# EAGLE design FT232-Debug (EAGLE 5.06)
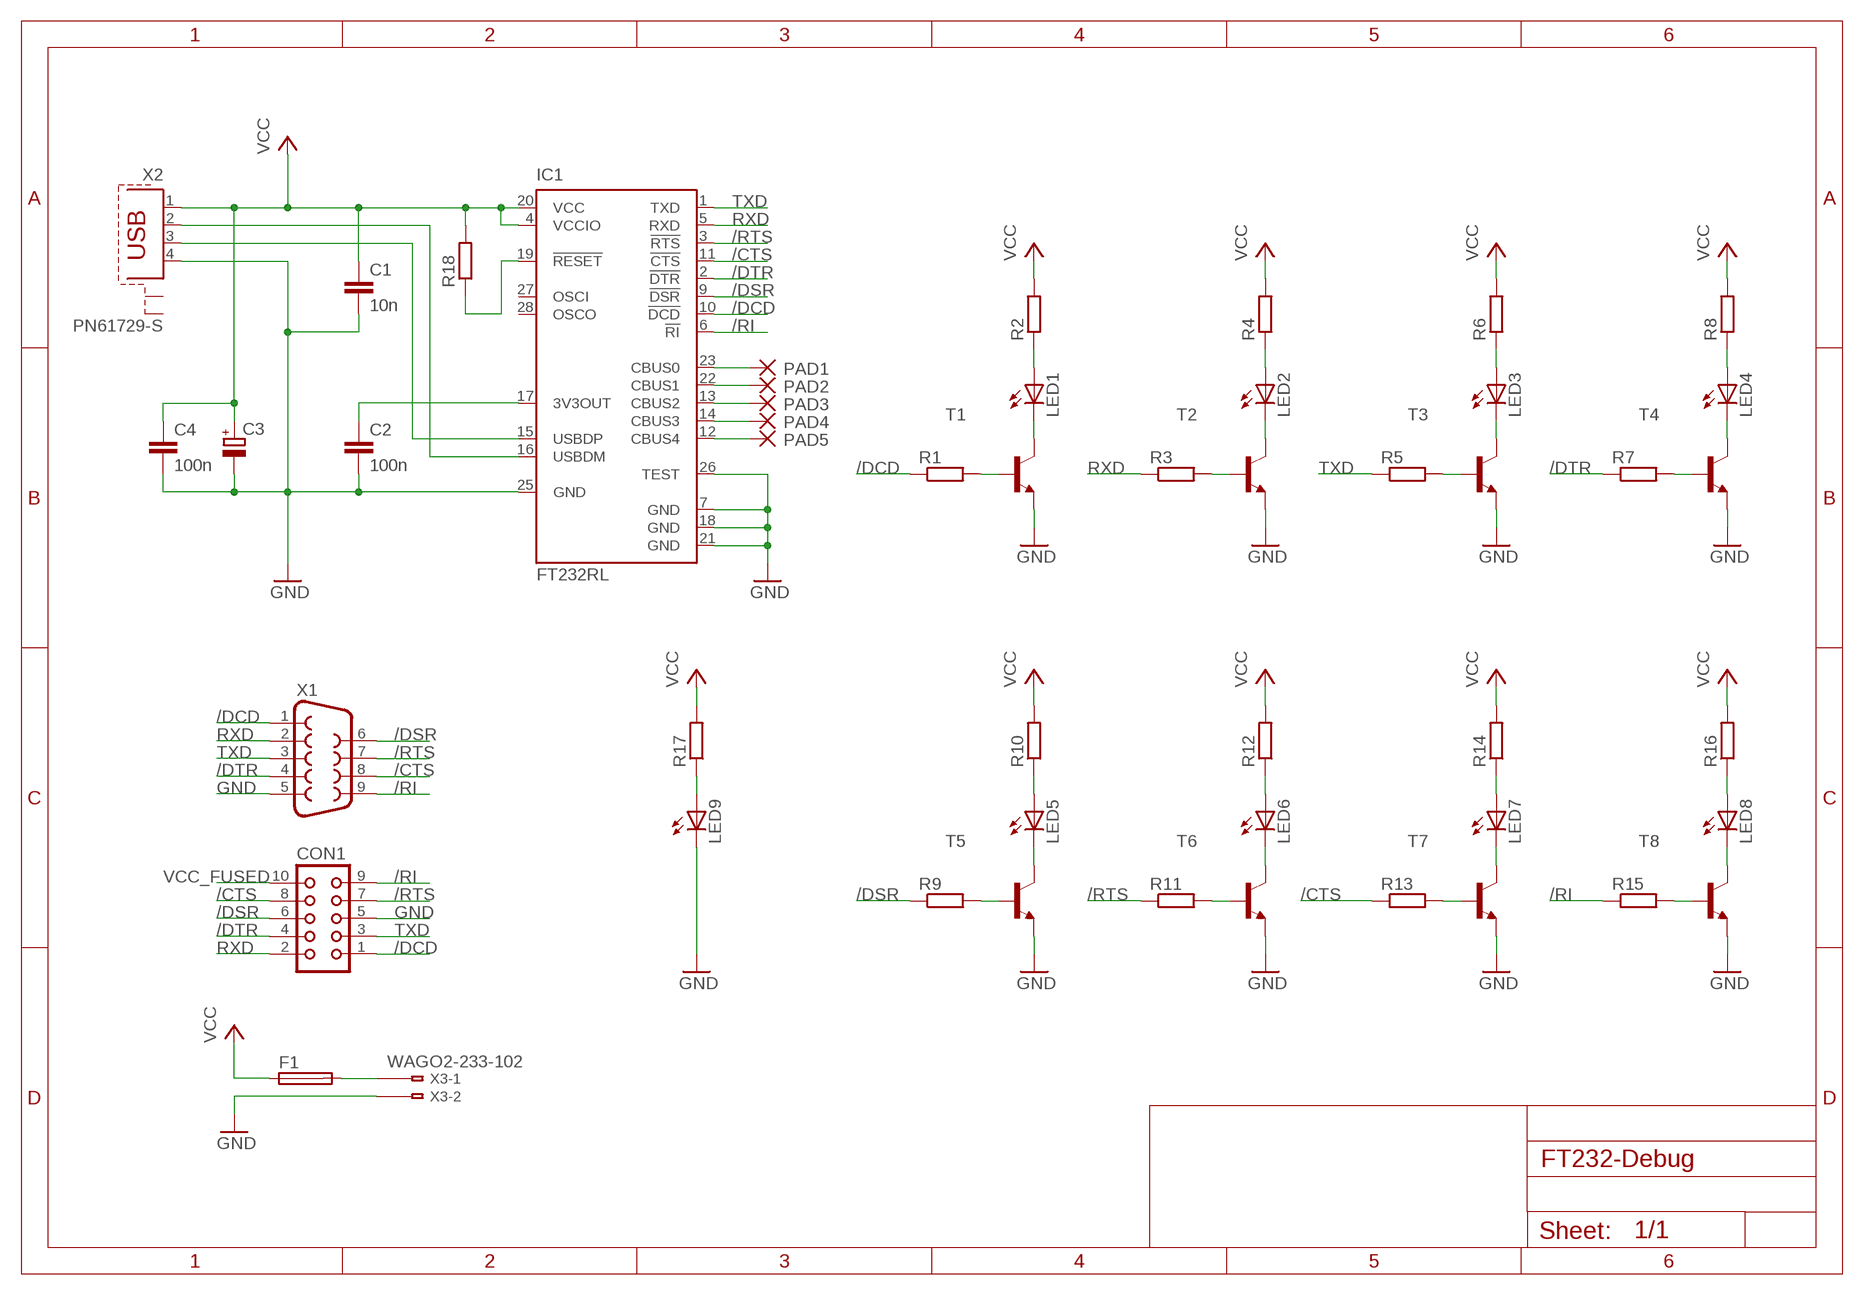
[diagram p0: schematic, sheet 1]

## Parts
C1  10n  C-EU025-025X050  [C025-025X050]
C2  100n  C-EU025-025X050  [C025-025X050]
C3  CPOL-EUE2,5-6E  [E2,5-6E]
C4  100n  C-EU025-025X050  [C025-025X050]
CON1  CON10  [CON10]
F1  SH22,5A  [SH22,5A]
IC1  FT232RL  [SSOP28]
LED1  LED3MM  [LED3MM]
LED2  LED3MM  [LED3MM]
LED3  LED3MM  [LED3MM]
LED4  LED3MM  [LED3MM]
LED5  LED3MM  [LED3MM]
LED6  LED3MM  [LED3MM]
LED7  LED3MM  [LED3MM]
LED8  LED3MM  [LED3MM]
LED9  LED3MM  [LED3MM]
PAD1  WIREPAD1,6/0,8  [1,6/0,8]
PAD2  WIREPAD1,6/0,8  [1,6/0,8]
PAD3  WIREPAD1,6/0,8  [1,6/0,8]
PAD4  WIREPAD1,6/0,8  [1,6/0,8]
PAD5  WIREPAD1,6/0,8  [1,6/0,8]
R1  R-EU_R0805  [R0805]
R2  R-EU_R0805  [R0805]
R3  R-EU_R0805  [R0805]
R4  R-EU_R0805  [R0805]
R5  R-EU_R0805  [R0805]
R6  R-EU_R0805  [R0805]
R7  R-EU_R0805  [R0805]
R8  R-EU_R0805  [R0805]
R9  R-EU_R0805  [R0805]
R10  R-EU_R0805  [R0805]
R11  R-EU_R0805  [R0805]
R12  R-EU_R0805  [R0805]
R13  R-EU_R0805  [R0805]
R14  R-EU_R0805  [R0805]
R15  R-EU_R0805  [R0805]
R16  R-EU_R0805  [R0805]
R17  R-EU_R0805  [R0805]
R18  R-EU_R0805  [R0805]
T1  BC847-NPN-SOT23-BEC  [SOT23-BEC]
T2  BC847-NPN-SOT23-BEC  [SOT23-BEC]
T3  BC847-NPN-SOT23-BEC  [SOT23-BEC]
T4  BC847-NPN-SOT23-BEC  [SOT23-BEC]
T5  BC847-NPN-SOT23-BEC  [SOT23-BEC]
T6  BC847-NPN-SOT23-BEC  [SOT23-BEC]
T7  BC847-NPN-SOT23-BEC  [SOT23-BEC]
T8  BC847-NPN-SOT23-BEC  [SOT23-BEC]
X1  F09HP  [F09HP]
X2  PN61729-S  [PN61729-S]
X3  WAGO2-233-102  [233-102]

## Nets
/CTS: CON1.8 IC1.11(!CTS) R13.1 X1.8
/DCD: CON1.1 IC1.10(!DCD) R1.1 X1.1
/DSR: CON1.6 IC1.9(!DSR) R9.1 X1.6
/DTR: CON1.4 IC1.2(!DTR) R7.1 X1.4
/RI: CON1.9 IC1.6(!RI) R15.1 X1.9
/RTS: CON1.7 IC1.3(!RTS) R11.1 X1.7
GND: C1.2 C2.2 C3.- C4.2 CON1.5 IC1.7(GND) IC1.18(GND) IC1.21(GND) IC1.25(GND) IC1.26(TEST) LED9.K(C) T1.E T2.E T3.E T4.E T5.E T6.E T7.E T8.E X1.5 X2.4 X3.B2(-2:B1)
N$1: R1.2 T1.B
N$2: IC1.16(USBDM) X2.2
N$3: IC1.15(USBDP) X2.3
N$4: C2.1 IC1.17(3V3OUT)
N$5: LED1.K(C) T1.C
N$7: LED1.A R2.1
N$8: R3.2 T2.B
N$9: LED2.K(C) T2.C
N$10: LED2.A R4.1
N$11: LED9.A R17.1
N$12: IC1.23(CBUS0) PAD1.1(P)
N$13: R5.2 T3.B
N$14: LED3.K(C) T3.C
N$15: LED3.A R6.1
N$16: IC1.22(CBUS1) PAD2.1(P)
N$17: R7.2 T4.B
N$18: LED4.K(C) T4.C
N$19: LED4.A R8.1
N$20: IC1.13(CBUS2) PAD3.1(P)
N$21: R9.2 T5.B
N$22: LED5.K(C) T5.C
N$23: LED5.A R10.1
N$24: IC1.14(CBUS3) PAD4.1(P)
N$25: R11.2 T6.B
N$26: LED6.K(C) T6.C
N$27: LED6.A R12.1
N$28: IC1.12(CBUS4) PAD5.1(P)
N$29: R13.2 T7.B
N$30: LED7.K(C) T7.C
N$31: LED7.A R14.1
N$33: R15.2 T8.B
N$34: LED8.K(C) T8.C
N$35: LED8.A R16.1
N$40: IC1.19(!RESET) R18.1
RXD: CON1.2 IC1.5(RXD) R3.1 X1.2
TXD: CON1.3 IC1.1(TXD) R5.1 X1.3
VCC: C1.1 C3.+ C4.1 F1.1 IC1.4(VCCIO) IC1.20(VCC) R2.2 R4.2 R6.2 R8.2 R10.2 R12.2 R14.2 R16.2 R17.2 R18.2 X2.1
VCC_FUSED: CON1.10 F1.2 X3.B1(-1:B1)
Unconnected: IC1.27(OSCI) IC1.28(OSCO) X2.S1 X2.S2 X3.A1(-1:A1) X3.A2(-2:A1)

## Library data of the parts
C1 C2 C4 = rcl:C-EU: CAPACITOR, European symbol
C3 = rcl:CPOL-EU: POLARIZED CAPACITOR, European symbol
CON1 = con-harting:CON10: CONNECTOR
F1 = fuse:SH22,5A: FUSE HOLDER
IC1 = ftdichip:FT232R: Source: http://www.ftdichip.com/Documents/DataSheets/DS_FT232R_v104.pdf
LED1-LED9 = led:LED: LED
PAD1-PAD5 = wirepad:WIREPAD: Wire PAD connect wire on PCB
R1-R18 = rcl:R-EU_: RESISTOR, European symbol
T1-T8 = transistor:*-NPN-: NPN Transistror BF959 corrected 2008.03.06
X1 = con-subd:F09: SUB-D
X2 = con-berg:PN61729-S: BERG USB connector
X3 = con-wago:WAGO2-: WAGO Cage Clamp

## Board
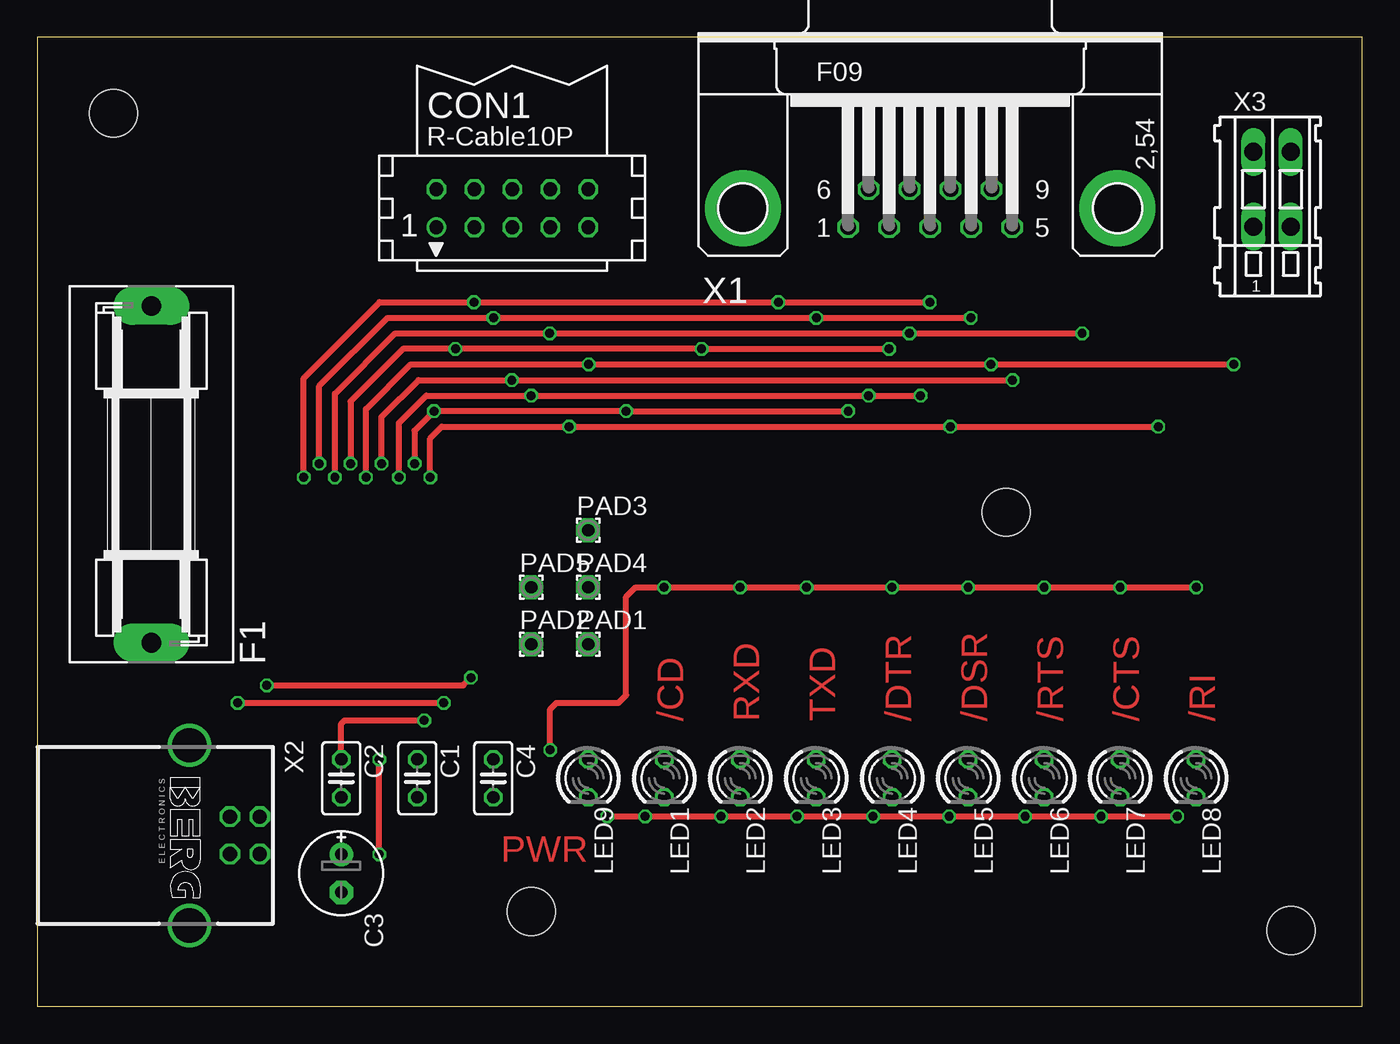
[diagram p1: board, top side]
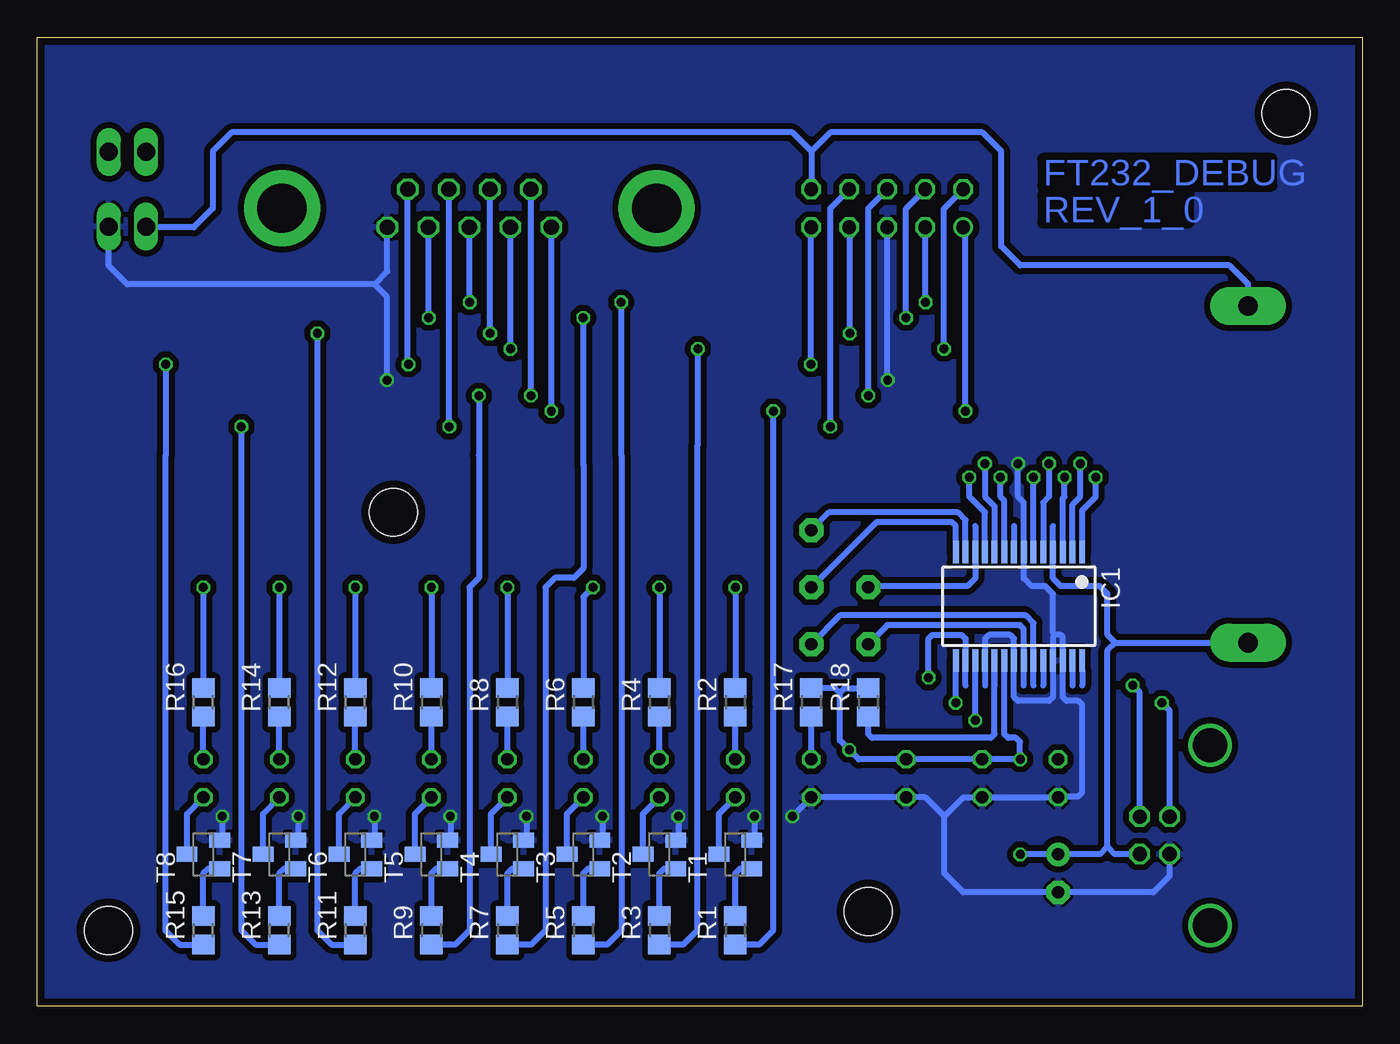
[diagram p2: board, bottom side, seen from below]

Size 88.57 x 64.76 mm. Coordinates in mm from the lower left corner, seen from the top.
Outline: 0,0 88.57,0 88.57,64.76 0,64.76 0,0
Copper layers (1*16): Top 0.035mm / dielectric 1.5mm / Bottom 0.035mm
Design rules "PCB-POOL": minimum track width 6mil, minimum drill 12mil, track to track 6mil, track to pad 6mil, pad to pad 6mil, via to via 6mil, smd to smd 6mil, copper to edge 20mil, drill to drill 8mil, minimum pad ring 8mil, minimum via ring 6mil, stop-mask expansion 3mil, vias tented up to drill 0mil, thermal gap 8mil
Holes 3.2 mm at 5.08,59.69 83.82,5.08 64.77,33.02 33.02,6.35

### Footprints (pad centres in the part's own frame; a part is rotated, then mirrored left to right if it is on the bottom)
C025-025X050 = drill 0.813 octagon: 1 -1.27,0; 2 1.27,0
E2,5-6E = drill 0.813 pad 1.575 round: + -1.27,0 | drill 0.813 pad 1.575 octagon: - 1.27,0
CON10 = drill 0.914 round: 1 -5.08,-1.27 | drill 0.914 octagon: 2 -5.08,1.27; 3 -2.54,-1.27; 4 -2.54,1.27; 5 0,-1.27; 6 0,1.27; 7 2.54,-1.27; 8 2.54,1.27; 9 5.08,-1.27; 10 5.08,1.27
SH22,5A = drill 1.321 pad 2.54 long: 1 -11.252,0; 2 11.252,0
SSOP28 = smd 0.4 x 1.5: 1 -4.225,-3.625; 2 -3.575,-3.625; 3 -2.925,-3.625; 4 -2.275,-3.625; 5 -1.625,-3.625; 6 -0.975,-3.625; 7 -0.325,-3.625; 8 0.325,-3.625; 9 0.975,-3.625; 10 1.625,-3.625; 11 2.275,-3.625; 12 2.925,-3.625; 13 3.575,-3.625; 14 4.225,-3.625; 15 4.225,3.625; 16 3.575,3.625; 17 2.925,3.625; 18 2.275,3.625; 19 1.625,3.625; 20 0.975,3.625; 21 0.325,3.625; 22 -0.325,3.625; 23 -0.975,3.625; 24 -1.625,3.625; 25 -2.275,3.625; 26 -2.925,3.625; 27 -3.575,3.625; 28 -4.225,3.625
LED3MM = drill 0.813 octagon: A -1.27,0; K 1.27,0
1,6/0,8 = drill 0.813 pad 1.6 octagon: 1 0,0
R0805 = smd 1.3 x 1.5: 1 -0.95,0; 2 0.95,0
SOT23-BEC = smd 1 x 1.4: B -0.95,-1.1; C 0,1.1; E 0.95,-1.1
F09HP = drill 1.016 octagon: 1 -5.486,-1.27; 2 -2.743,-1.27; 3 0,-1.27; 4 2.743,-1.27; 5 5.486,-1.27; 6 -4.115,1.27; 7 -1.372,1.27; 8 1.372,1.27; 9 4.115,1.27 | drill 3.302 pad 5.08 round: G1 -12.522,0; G2 12.522,0
PN61729-S = drill 0.95 octagon: 1 1.25,4.71; 2 -1.25,4.71; 3 -1.25,2.71; 4 1.25,2.71 | drill 2.3 pad 2.9 round: S1 -6.02,0; S2 6.02,0
233-102 = drill 1.2 long: A1 -1.25,2.5; A2 1.25,2.5; B1 -1.25,-2.5; B2 1.25,-2.5

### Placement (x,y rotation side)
C1  25.4,15.24 270 top
C2  20.32,15.24 270 top
C3  20.32,8.89 270 top
C4  30.48,15.24 270 top
CON1  31.75,53.34 0 top
F1  7.62,35.56 90 top
IC1  22.95,26.74 180 bottom
LED1  41.91,15.24 270 top
LED2  46.99,15.24 270 top
LED3  52.07,15.24 270 top
LED4  57.15,15.24 270 top
LED5  62.23,15.24 270 top
LED6  67.31,15.24 270 top
LED7  72.39,15.24 270 top
LED8  77.47,15.24 270 top
LED9  36.83,15.24 270 top
PAD1  36.83,24.2 0 top
PAD2  33.02,24.2 0 top
PAD3  36.83,31.82 0 top
PAD4  36.83,28.01 0 top
PAD5  33.02,28.01 0 top
R1  41.91,5.08 90 bottom
R2  41.91,20.32 90 bottom
R3  46.99,5.08 90 bottom
R4  46.99,20.32 90 bottom
R5  52.07,5.08 90 bottom
R6  52.07,20.32 90 bottom
R7  57.15,5.08 90 bottom
R8  57.15,20.32 90 bottom
R9  62.23,5.08 90 bottom
R10  62.23,20.32 90 bottom
R11  67.31,5.08 90 bottom
R12  67.31,20.32 90 bottom
R13  72.39,5.08 90 bottom
R14  72.39,20.32 90 bottom
R15  77.47,5.08 90 bottom
R16  77.47,20.32 90 bottom
R17  36.83,20.32 90 bottom
R18  33.02,20.32 90 bottom
T1  41.91,10.16 90 bottom
T2  46.99,10.16 90 bottom
T3  52.07,10.16 90 bottom
T4  57.15,10.16 90 bottom
T5  62.23,10.16 90 bottom
T6  67.31,10.16 90 bottom
T7  72.39,10.16 90 bottom
T8  77.47,10.16 90 bottom
X1  59.69,53.34 0 top
X2  10.16,11.43 270 top
X3  82.55,54.61 0 top

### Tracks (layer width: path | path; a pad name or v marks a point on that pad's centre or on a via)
/CTS  (via drill 0.6)
  Top 0.406: v26.26,35.36 26.26,37.96 27.04,38.74 v35.55,38.74 v61.03,38.74 v74.93,38.74
  Bottom 0.406: v26.26,35.36 26.26,34.06 25.22,33.02 IC1.11 | CON1.8 35.56,53.34 35.55,53.34 v35.55,38.74 | X1.8 61.03,54.61 v61.03,38.74 | R13.1 73.98,4.13 74.93,5.08 v74.93,38.74
/DCD  (via drill 0.6)
  Top 0.406: v25.22,36.27 25.22,38.48 v26.52,39.78 v39.37,39.78 v54.21,39.78
  Bottom 0.406: v25.22,36.27 25.22,34.06 24.57,33.41 IC1.10 | v26.52,39.78 26.52,51.92 CON1.1 | X1.1 v54.21,39.78 | R1.1 40.32,4.13 39.37,5.08 v39.37,39.78
/DSR  (via drill 0.6)
  Top 0.406: v24.18,35.36 24.18,39 26,40.82 v33.02,40.82 v55.58,40.82 v59.05,40.82
  Bottom 0.406: v24.18,35.36 24.18,34.06 23.92,33.8 IC1.9 | CON1.6 33.02,53.34 v33.02,40.82 | X1.6 | v55.58,40.82 X1.6 | R9.1 60.64,4.13 59.69,5.08 59.69,28 59.05,28.64 59.05,36.83 59.05,36.84 v59.05,40.82
/DTR  (via drill 0.6)
  Top 0.406: v18.85,36.27 18.85,41.47 23.4,46.02 v30.48,46.02 v52.08,46.02 v62.4,46.02
  Bottom 0.406: v18.85,36.27 18.85,34.06 19.37,33.54 IC1.2 | CON1.4 30.48,53.34 v30.48,46.02 | X1.4 62.4,52.07 v62.4,46.02 | R7.1 55.56,4.13 54.61,5.08 54.61,28 53.98,28.64 52.7,28.64 52.07,29.27 52.07,36.2 52.08,36.2 v52.08,46.02
/RI  (via drill 0.6)
  Top 0.406: v21.97,35.36 21.97,39.91 24.96,42.9 v36.85,42.9 v63.77,42.9 v79.98,42.9
  Bottom 0.406: IC1.6 v21.97,35.36 | CON1.9 36.85,52.07 v36.85,42.9 | v63.77,42.9 63.8,42.9 X1.9 | R15.1 79.06,4.13 80.01,5.08 80.01,36.83 79.98,36.86 v79.98,42.9
/RTS  (via drill 0.6)
  Top 0.406: v19.89,35.36 19.89,40.95 23.92,44.98 v34.26,44.98 v58.3,44.98 v69.85,44.98
  Bottom 0.406: v19.89,35.36 19.89,34.06 20.02,33.93 IC1.3 | CON1.7 34.26,52.07 v34.26,44.98 | v58.3,44.98 58.32,44.98 X1.7 | R11.1 68.9,4.13 69.85,5.08 v69.85,44.98
GND  (via drill 0.6)
  Top 0.406: v23.01,36.27 23.01,39.39 25.48,41.86 v31.72,41.86 v65.19,41.86 | v76.2,12.7 v71.12,12.7 v66.04,12.7 v60.96,12.7 v55.88,12.7 v50.8,12.7 v45.72,12.7 v40.64,12.7 v38.1,12.7
  Bottom 0.406: v23.01,36.27 23.01,34.06 22.62,33.67 IC1.7 22.62,28.6 22.1,28.08 21.19,28.08 20.67,27.56 20.67,24.96 20.54,24.83 | CON1.5 31.72,52.07 v31.72,41.86 | T1.E 40.64,11.11 v40.64,12.7 | v45.72,12.7 45.72,11.11 T2.E | T3.E 50.8,11.11 v50.8,12.7 | T4.E 55.88,11.11 v55.88,12.7 | T5.E 60.96,11.11 v60.96,12.7 | T6.E 66.04,11.11 v66.04,12.7 | T7.E 71.12,11.11 v71.12,12.7 | T8.E 76.2,11.11 v76.2,12.7 | v38.1,12.7 LED9.K C4.2 29.21,13.97 27.94,12.7 | X2.4 12.87,8.72 13.97,7.62 C3.- 26.67,7.62 27.94,8.89 27.94,12.7 | 27.94,12.7 26.67,13.97 C1.2 C2.2 20.25,14.04 18.98,14.04 18.72,14.3 18.72,20.15 18.98,20.41 19.76,20.41 20.02,20.67 IC1.26 20.02,24.7 20.15,24.83 20.54,24.83 | X3.B2 83.8,49.51 82.55,48.26 66.04,48.26 | v65.19,41.86 65.19,47.41 66.04,48.26 | X1.5 65.18,49.12 66.04,48.26 | IC1.18 25.22,24.57 24.96,24.83 23.53,24.83 23.27,24.57 IC1.21 23.27,20.67 23.01,20.41 20.93,20.41 20.67,20.67 IC1.25 20.67,24.7 20.54,24.83
  pour Bottom (isolate 0.406): -1.27,66.04 90.17,66.04 90.17,-1.27 -1.27,-1.27
N$1
  Bottom 0.406: T1.B 41.59,9.21 41.91,8.89 R1.2
N$2  (via drill 0.6)
  Top 0.406: v15.34,21.45 28.47,21.45 v28.99,21.97
  Bottom 0.406: X2.2 14.87,20.98 v15.34,21.45 | IC1.16 26.52,24.57 26.78,24.83 28.73,24.83 28.99,24.57 v28.99,21.97
N$3  (via drill 0.6)
  Top 0.406: v13.39,20.28 26.39,20.28 | 26.39,20.28 26.52,20.28 | 26.39,20.28 v27.17,20.28
  Bottom 0.406: X2.3 12.87,19.76 v13.39,20.28 | v27.17,20.28 IC1.15
N$4  (via drill 0.6)
  Top 0.406: C2.1 20.32,18.89 20.54,19.11 v25.87,19.11
  Bottom 0.406: v25.87,19.11 IC1.17
N$5
  Bottom 0.406: T1.C 43.01,12.87 LED1.K
N$6
  Bottom 0.406: 25.87,32.11 25.87,30.68
N$7
  Bottom 0.406: LED1.A R2.1
N$8
  Bottom 0.406: T2.B 46.67,9.21 46.99,8.89 R3.2
N$9
  Bottom 0.406: T2.C 48.09,12.87 LED2.K
N$10
  Bottom 0.406: LED2.A R4.1
N$11
  Bottom 0.406: LED9.A R17.1
N$12
  Bottom 0.406: IC1.23 21.97,25.61 22.49,26.13 34.9,26.13 PAD1.1
N$13
  Bottom 0.406: T3.B 51.75,9.21 52.07,8.89 R5.2
N$14
  Bottom 0.406: T3.C 53.17,12.87 LED3.K
N$15
  Bottom 0.406: LED3.A R6.1
N$16
  Bottom 0.406: IC1.22 22.62,25.22 22.88,25.48 31.74,25.48 PAD2.1
N$17
  Bottom 0.406: T4.B 56.83,9.21 57.15,8.89 R7.2
N$18
  Bottom 0.406: T4.C 58.25,12.87 LED4.K
N$19
  Bottom 0.406: LED4.A R8.1
N$20
  Bottom 0.406: IC1.13 26.52,32.5 27.04,33.02 35.63,33.02 PAD3.1
N$21
  Bottom 0.406: T5.B 61.91,9.21 62.23,8.89 R9.2
N$22
  Bottom 0.406: T5.C 63.33,12.87 LED5.K
N$23
  Bottom 0.406: LED5.A R10.1
N$24
  Bottom 0.406: IC1.14 27.17,32.11 27.43,32.37 32.47,32.37 PAD4.1
N$25
  Bottom 0.406: T6.B 66.99,9.21 67.31,8.89 R11.2
N$26
  Bottom 0.406: T6.C 68.41,12.87 LED6.K
N$27
  Bottom 0.406: LED6.A R12.1
N$28
  Bottom 0.406: IC1.12 25.87,28.6 26.39,28.08 32.95,28.08 PAD5.1
N$29
  Bottom 0.406: T7.B 72.07,9.21 72.39,8.89 R13.2
N$30
  Bottom 0.406: T7.C 73.49,12.87 LED7.K
N$31
  Bottom 0.406: LED7.A R14.1
N$32
  Bottom 0.406: 23.27,32.11 23.27,30.81
N$33
  Bottom 0.406: T8.B 77.15,9.21 77.47,8.89 R15.2
N$34
  Bottom 0.406: T8.C 78.57,12.87 LED8.K
N$35
  Bottom 0.406: LED8.A R16.1
N$36
  Bottom 0.406: 20.67,30.42 20.67,32.11
N$37
  Bottom 0.406: 21.97,21.45 21.97,22.49
N$38
  Bottom 0.406: 22.62,21.45 22.62,22.62
N$39
  Bottom 0.406: 21.32,22.49 21.32,21.45
N$40
  Bottom 0.406: IC1.19 24.57,18.2 24.83,17.94 32.76,17.94 33.02,18.2 R18.1
N$41
  Bottom 0.406: 18.72,22.49 18.72,21.45
N$42
  Bottom 0.406: 19.37,22.49 19.37,21.45
N$43
  Bottom 0.406: 24.57,22.49 24.57,21.45
N$44
  Bottom 0.406: 25.22,22.62 25.22,21.45
N$45
  Bottom 0.406: 25.87,21.45 25.87,23.14
N$46
  Bottom 0.406: 26.52,21.45 26.52,23.01
N$47
  Bottom 0.406: 27.17,21.45 27.17,23.14
RXD  (via drill 0.6)
  Top 0.406: v20.93,36.27 20.93,40.43 24.44,43.94 v27.95,43.94 v44.4,43.94 v56.94,43.94
  Bottom 0.406: IC1.5 21.32,33.67 20.93,34.06 v20.93,36.27 | CON1.2 27.94,53.34 27.95,53.34 v27.95,43.94 | X1.2 v56.94,43.94 | R3.1 45.4,4.13 44.45,5.08 44.45,37.47 44.4,37.51 v44.4,43.94
TXD  (via drill 0.6)
  Top 0.406: v17.81,35.36 17.81,41.99 22.88,47.06 v29.18,47.06 v49.54,47.06 v59.67,47.06
  Bottom 0.406: v17.81,35.36 17.81,34.06 18.72,33.15 IC1.1 | CON1.3 29.18,52.07 v29.18,47.06 | X1.3 59.67,52.07 v59.67,47.06 | R5.1 50.48,4.13 49.53,5.08 49.53,36.83 49.54,36.84 v49.54,47.06
VCC  (via drill 0.6)
  Top 0.406: v77.47,28 v72.39,28 v67.31,28 v62.23,28 v57.15,28 v51.44,28 v46.99,28 v41.91,28 40.01,28 39.37,27.37 39.37,20.8 38.85,20.28 34.71,20.28 34.29,19.86 v34.29,17.14 | v22.86,10.16 v22.86,16.51
  Bottom 0.406: v41.91,28 R2.2 | v46.99,28 R4.2 | R6.2 52.07,27.37 v51.44,28 | v57.15,28 R8.2 | v62.23,28 R10.2 | v67.31,28 R12.2 | v72.39,28 R14.2 | v77.47,28 R16.2 | v22.86,10.16 C3.+ 20.3,10.18 17.51,10.18 17.03,10.66 | IC1.20 23.92,18.2 23.66,17.94 23.14,17.94 22.88,17.68 22.88,16.53 v22.86,16.51 C1.1 C4.1 33.66,16.51 v34.29,17.14 34.92,17.78 34.92,20.95 | X2.1 16.55,10.18 17.03,10.66 | 17.03,10.66 17.03,23.79 16.51,24.31 | IC1.4 20.67,28.6 20.15,28.08 17.55,28.08 17.03,27.56 17.03,24.83 16.51,24.31 | F1.1 16.51,24.31 | 36.75,21.19 R17.2 35.24,21.27 34.92,20.95 | R18.2 34.61,21.27 34.92,20.95
VCC_FUSED
  Bottom 0.406: 36.83,57.15 CON1.10 | 36.83,57.15 38.1,58.42 75.56,58.42 76.83,57.15 76.83,53.34 78.11,52.07 81.26,52.07 X3.B1 | 36.83,57.15 35.56,58.42 25.4,58.42 24.13,57.15 24.13,53.34 24.13,50.8 22.86,49.53 8.89,49.53 7.62,48.26 F1.2

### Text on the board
Top: /CD | RXD | TXD | /DTR | /DSR | /RTS | /CTS | /RI | PWR
Bottom: FT232_DEBUG | REV_1_0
